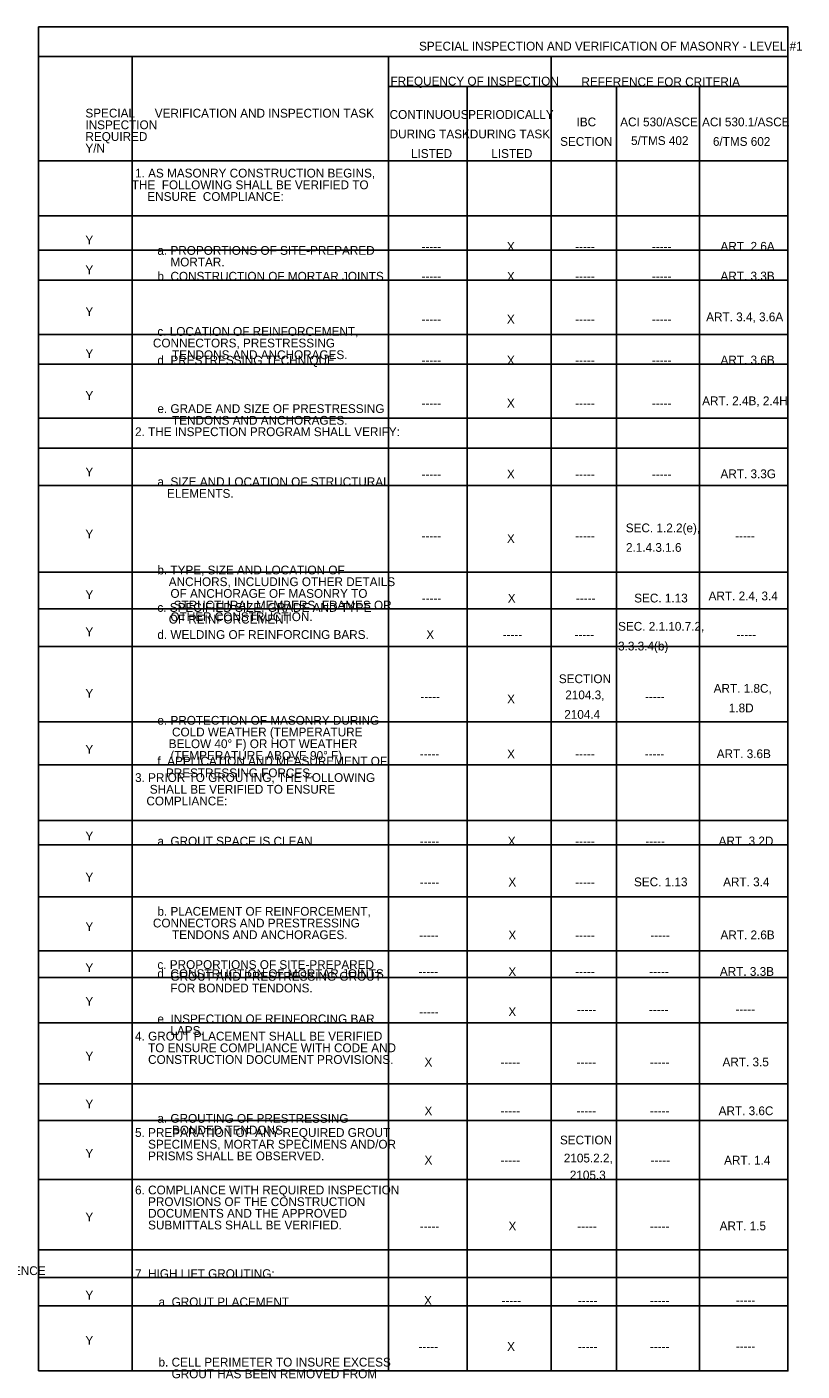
# Model space of a CAD drawing. Extents: x 2632118 to 2632142.4, y 1706724.1 to 1706788.4.
# Drawn here: x 2632127.48 to 2632134.83, y 1706755.03 to 1706767.77 of the extents above; entities that cross this region are included whole.
import ezdxf

# ---------------------------------------------------------------- set-up
doc = ezdxf.new("R2010")
doc.units = 0
doc.layers.add('Default', color=7, linetype='Continuous')

msp = doc.modelspace()

# ---------------------------------------------------------------- linework, layer by layer
at = {"layer": 'Default'}
for p, q in [((2632128.477, 1706767.493), (2632128.477, 1706755.032)), ((2632130.909, 1706767.493), (2632130.909, 1706755.032)), ((2632132.454, 1706767.493), (2632132.454, 1706755.032)), ((2632134.699, 1706767.211), (2632130.909, 1706767.211)), ((2632131.655, 1706767.211), (2632131.655, 1706755.032)), ((2632133.074, 1706767.211), (2632133.074, 1706755.032)), ((2632133.861, 1706767.211), (2632133.861, 1706755.032)), ((2632134.699, 1706766.505), (2632127.588, 1706766.505)), ((2632134.699, 1706765.984), (2632127.588, 1706765.984)), ((2632134.699, 1706765.657), (2632127.588, 1706765.657)), ((2632134.699, 1706765.374), (2632127.588, 1706765.374)), ((2632134.699, 1706764.86), (2632127.588, 1706764.86)), ((2632134.699, 1706764.578), (2632127.588, 1706764.578)), ((2632134.699, 1706764.064), (2632127.588, 1706764.064)), ((2632134.699, 1706763.782), (2632127.588, 1706763.782)), ((2632134.699, 1706763.427), (2632127.588, 1706763.427)), ((2632134.699, 1706762.604), (2632127.588, 1706762.604)), ((2632134.699, 1706762.256), (2632127.588, 1706762.256)), ((2632134.699, 1706761.899), (2632127.588, 1706761.899)), ((2632134.699, 1706761.187), (2632127.588, 1706761.187)), ((2632134.699, 1706760.777), (2632127.588, 1706760.777)), ((2632134.699, 1706760.25), (2632127.588, 1706760.25)), ((2632134.699, 1706760.019), (2632127.588, 1706760.019)), ((2632134.699, 1706759.528), (2632127.588, 1706759.528)), ((2632134.699, 1706759.015), (2632127.588, 1706759.015)), ((2632134.699, 1706758.762), (2632127.588, 1706758.762)), ((2632134.699, 1706758.334), (2632127.588, 1706758.334)), ((2632134.699, 1706757.753), (2632127.588, 1706757.753)), ((2632134.699, 1706757.405), (2632127.588, 1706757.405)), ((2632134.699, 1706756.846), (2632127.588, 1706756.846)), ((2632134.699, 1706756.179), (2632127.588, 1706756.179)), ((2632134.699, 1706755.919), (2632127.588, 1706755.919)), ((2632134.699, 1706755.651), (2632127.588, 1706755.651))]:
    msp.add_line(p, q, dxfattribs=at)
msp.add_lwpolyline([(2632127.588, 1706755.032), (2632134.699, 1706755.032), (2632134.699, 1706767.775), (2632127.588, 1706767.775)], close=True, dxfattribs=at)
msp.add_lwpolyline([(2632134.699, 1706767.493), (2632127.588, 1706767.493)], dxfattribs=at)

# ---------------------------------------------------------------- texts
for s, height, p in [('SPECIAL INSPECTION AND VERIFICATION OF MASONRY - LEVEL #1 ', 0.08333, (2632131.199, 1706767.551)), ('FREQUENCY OF INSPECTION ', 0.08333, (2632130.928, 1706767.219)), ('REFERENCE FOR CRITERIA', 0.08333, (2632132.74, 1706767.213)), ('SPECIAL ', 0.0833, (2632128.033, 1706766.916)), ('VERIFICATION AND INSPECTION TASK ', 0.08333, (2632128.691, 1706766.915)), ('INSPECTION ', 0.08333, (2632128.033, 1706766.805)), ('CONTINUOUS', 0.0833, (2632130.92, 1706766.903)), ('PERIODICALLY', 0.08333, (2632131.665, 1706766.903)), ('IBC', 0.0833, (2632132.694, 1706766.832)), ('ACI 530/ASCE', 0.08333, (2632133.108, 1706766.832)), ('ACI 530.1/ASCE', 0.08333, (2632133.885, 1706766.832)), ('REQUIRED', 0.0833, (2632128.033, 1706766.694)), ('DURING TASK', 0.08333, (2632130.92, 1706766.718)), ('DURING TASK', 0.08333, (2632131.681, 1706766.718)), ('5/TMS 402', 0.0833, (2632133.211, 1706766.655)), ('Y/N', 0.0833, (2632128.033, 1706766.583)), ('LISTED', 0.0833, (2632131.123, 1706766.533)), ('LISTED', 0.0833, (2632131.885, 1706766.533)), ('SECTION', 0.0833, (2632132.538, 1706766.647)), ('6/TMS 602', 0.0833, (2632133.988, 1706766.647)), ('1. AS MASONRY CONSTRUCTION BEGINS, ', 0.08333, (2632128.504, 1706766.347)), ('   THE  FOLLOWING SHALL BE VERIFIED TO ', 0.08333, (2632128.38, 1706766.236)), ('   ENSURE  COMPLIANCE:', 0.08333, (2632128.528, 1706766.125)), ('Y', 0.0833, (2632128.033, 1706765.712)), ('X', 0.0833, (2632132.033, 1706765.651)), ('ART. 2.6A', 0.0833, (2632134.06, 1706765.653)), ('a. PROPORTIONS OF SITE-PREPARED ', 0.08333, (2632128.716, 1706765.614)), ('-----', 0.0833, (2632131.223, 1706765.651)), ('-----', 0.0833, (2632132.681, 1706765.651)), ('-----', 0.0833, (2632133.409, 1706765.651)), ('Y', 0.0833, (2632128.033, 1706765.43)), ('    MORTAR.', 0.08333, (2632128.716, 1706765.504)), ('b. CONSTRUCTION OF MORTAR JOINTS.', 0.08333, (2632128.716, 1706765.369)), ('-----', 0.0833, (2632131.223, 1706765.369)), ('X', 0.0833, (2632132.033, 1706765.369)), ('-----', 0.0833, (2632132.681, 1706765.369)), ('-----', 0.0833, (2632133.409, 1706765.369)), ('ART. 3.3B', 0.0833, (2632134.06, 1706765.371)), ('Y', 0.0833, (2632128.033, 1706765.034)), ('-----', 0.0833, (2632131.223, 1706764.962)), ('X', 0.0833, (2632132.033, 1706764.962)), ('-----', 0.0833, (2632132.681, 1706764.962)), ('-----', 0.0833, (2632133.409, 1706764.962)), ('ART. 3.4, 3.6A', 0.08333, (2632133.924, 1706764.984)), ('c. LOCATION OF REINFORCEMENT, ', 0.08333, (2632128.716, 1706764.846)), ('Y', 0.0833, (2632128.033, 1706764.636)), ('    CONNECTORS, PRESTRESSING ', 0.08333, (2632128.55, 1706764.736)), ('    TENDONS AND ANCHORAGES.', 0.08333, (2632128.731, 1706764.625)), ('d. PRESTRESSING TECHNIQUE', 0.08333, (2632128.716, 1706764.573)), ('-----', 0.0833, (2632131.223, 1706764.573)), ('X', 0.0833, (2632132.033, 1706764.573)), ('-----', 0.0833, (2632132.681, 1706764.573)), ('-----', 0.0833, (2632133.409, 1706764.573)), ('ART. 3.6B', 0.0833, (2632134.06, 1706764.575)), ('Y', 0.0833, (2632128.033, 1706764.238)), ('e. GRADE AND SIZE OF PRESTRESSING ', 0.08333, (2632128.716, 1706764.114)), ('-----', 0.0833, (2632131.223, 1706764.166)), ('X', 0.0833, (2632132.033, 1706764.166)), ('-----', 0.0833, (2632132.681, 1706764.166)), ('-----', 0.0833, (2632133.409, 1706764.166)), ('ART. 2.4B, 2.4H', 0.08333, (2632133.886, 1706764.188)), ('    TENDONS AND ANCHORAGES.', 0.08333, (2632128.731, 1706764.003)), ('2. THE INSPECTION PROGRAM SHALL VERIFY:', 0.08333, (2632128.504, 1706763.895)), ('Y', 0.0833, (2632128.033, 1706763.514)), ('X', 0.0833, (2632132.033, 1706763.494)), ('ART. 3.3G', 0.0833, (2632134.06, 1706763.496)), ('a. SIZE AND LOCATION OF STRUCTURAL ', 0.08333, (2632128.716, 1706763.421)), ('-----', 0.0833, (2632131.223, 1706763.494)), ('-----', 0.0833, (2632132.681, 1706763.494)), ('-----', 0.0833, (2632133.409, 1706763.494)), ('    ELEMENTS.', 0.08333, (2632128.684, 1706763.31)), ('SEC. 1.2.2(e),', 0.08333, (2632133.161, 1706762.983)), ('Y', 0.0833, (2632128.033, 1706762.925)), ('-----', 0.0833, (2632131.223, 1706762.907)), ('X', 0.0833, (2632132.033, 1706762.882)), ('-----', 0.0833, (2632132.681, 1706762.907)), ('-----', 0.0833, (2632134.199, 1706762.907)), ('2.1.4.3.1.6', 0.08333, (2632133.163, 1706762.798)), ('b. TYPE, SIZE AND LOCATION OF ', 0.08333, (2632128.716, 1706762.584)), ('    ANCHORS, INCLUDING OTHER DETAILS ', 0.08333, (2632128.7, 1706762.473)), ('Y', 0.0833, (2632128.033, 1706762.35)), ('    OF ANCHORAGE OF MASONRY TO', 0.08333, (2632128.716, 1706762.362)), ('ART. 2.4, 3.4', 0.08333, (2632133.947, 1706762.338)), ('c. SPECIFIED SIZE, GRADE AND TYPE ', 0.08333, (2632128.716, 1706762.229)), ('    STRUCTURAL MEMBERS, FRAMES OR ', 0.08333, (2632128.747, 1706762.251)), ('-----', 0.0833, (2632131.225, 1706762.316)), ('X', 0.0833, (2632132.041, 1706762.316)), ('-----', 0.0833, (2632132.688, 1706762.316)), ('SEC. 1.13', 0.0833, (2632133.241, 1706762.318)), ('    OF REINFORCEMENT', 0.08333, (2632128.7, 1706762.118)), ('    OTHER CONSTRUCTION.', 0.08333, (2632128.716, 1706762.141)), ('Y', 0.0833, (2632128.033, 1706761.998)), ('d. WELDING OF REINFORCING BARS.', 0.08333, (2632128.716, 1706761.972)), ('X', 0.0833, (2632131.268, 1706761.972)), ('SEC. 2.1.10.7.2,', 0.08333, (2632133.088, 1706762.05)), ('-----', 0.0833, (2632131.993, 1706761.972)), ('-----', 0.0833, (2632132.675, 1706761.972)), ('3.3.3.4(b)', 0.0833, (2632133.088, 1706761.863)), ('-----', 0.0833, (2632134.212, 1706761.972)), ('SECTION', 0.0833, (2632132.526, 1706761.553)), ('ART. 1.8C,', 0.0833, (2632133.995, 1706761.462)), ('Y', 0.0833, (2632128.033, 1706761.415)), ('-----', 0.0833, (2632131.212, 1706761.385)), ('X', 0.0833, (2632132.035, 1706761.361)), ('2104.3,', 0.0833, (2632132.587, 1706761.4)), ('-----', 0.0833, (2632133.344, 1706761.385)), ('2104.4', 0.0833, (2632132.577, 1706761.215)), ('1.8D', 0.0833, (2632134.139, 1706761.276)), ('e. PROTECTION OF MASONRY DURING ', 0.08333, (2632128.716, 1706761.159)), ('    COLD WEATHER (TEMPERATURE ', 0.08333, (2632128.731, 1706761.048)), ('    BELOW 40%%d F) OR HOT WEATHER', 0.08333, (2632128.7, 1706760.937)), ('Y', 0.0833, (2632128.033, 1706760.884)), ('    (TEMPERATURE ABOVE 90%%d F)', 0.08333, (2632128.716, 1706760.826)), ('X', 0.0833, (2632132.035, 1706760.84)), ('ART. 3.6B', 0.0833, (2632134.024, 1706760.842)), ('f. APPLICATION AND MEASUREMENT OF ', 0.08333, (2632128.716, 1706760.772)), ('-----', 0.0833, (2632131.206, 1706760.84)), ('-----', 0.0833, (2632132.681, 1706760.84)), ('-----', 0.0833, (2632133.341, 1706760.84)), ('3. PRIOR TO GROUTING, THE FOLLOWING ', 0.08333, (2632128.504, 1706760.616)), ('   PRESTRESSING FORCES.', 0.08333, (2632128.704, 1706760.661)), ('    SHALL BE VERIFIED TO ENSURE ', 0.08333, (2632128.52, 1706760.505)), ('    COMPLIANCE:', 0.08333, (2632128.488, 1706760.394)), ('Y', 0.0833, (2632128.033, 1706760.062)), ('a. GROUT SPACE IS CLEAN.', 0.08333, (2632128.716, 1706760.013)), ('-----', 0.0833, (2632131.206, 1706760.013)), ('X', 0.0833, (2632132.041, 1706760.013)), ('-----', 0.0833, (2632132.681, 1706760.013)), ('-----', 0.0833, (2632133.347, 1706760.013)), ('ART. 3.2D', 0.0833, (2632134.042, 1706760.015)), ('Y', 0.0833, (2632128.033, 1706759.672)), ('-----', 0.0833, (2632131.206, 1706759.625)), ('X', 0.0833, (2632132.047, 1706759.625)), ('-----', 0.0833, (2632132.681, 1706759.625)), ('SEC. 1.13', 0.0833, (2632133.239, 1706759.627)), ('ART. 3.4', 0.0833, (2632134.085, 1706759.627)), ('b. PLACEMENT OF REINFORCEMENT, ', 0.08333, (2632128.716, 1706759.348)), ('Y', 0.0833, (2632128.033, 1706759.203)), ('    CONNECTORS AND PRESTRESSING ', 0.08333, (2632128.55, 1706759.237)), ('    TENDONS AND ANCHORAGES. ', 0.08333, (2632128.731, 1706759.126)), ('-----', 0.0833, (2632131.2, 1706759.123)), ('X', 0.0833, (2632132.047, 1706759.123)), ('-----', 0.0833, (2632132.681, 1706759.123)), ('-----', 0.0833, (2632133.394, 1706759.123)), ('ART. 2.6B', 0.0833, (2632134.06, 1706759.125)), ('Y', 0.0833, (2632128.033, 1706758.813)), ('c. PROPORTIONS OF SITE-PREPARED ', 0.08333, (2632128.716, 1706758.843)), ('d. CONSTRUCTION OF MORTAR JOINTS.', 0.08333, (2632128.716, 1706758.757)), ('X', 0.0833, (2632132.047, 1706758.776)), ('ART. 3.3B', 0.0833, (2632134.054, 1706758.778)), ('    GROUT AND PRESTRESSING GROUT ', 0.08333, (2632128.716, 1706758.732)), ('-----', 0.0833, (2632131.194, 1706758.776)), ('-----', 0.0833, (2632132.681, 1706758.776)), ('-----', 0.0833, (2632133.384, 1706758.776)), ('    FOR BONDED TENDONS. ', 0.08333, (2632128.716, 1706758.621)), ('Y', 0.0833, (2632128.033, 1706758.494)), ('X', 0.0833, (2632132.047, 1706758.396)), ('-----', 0.0833, (2632134.202, 1706758.42)), ('e. INSPECTION OF REINFORCING BAR ', 0.08333, (2632128.716, 1706758.328)), ('-----', 0.0833, (2632131.2, 1706758.396)), ('-----', 0.0833, (2632132.696, 1706758.417)), ('-----', 0.0833, (2632133.381, 1706758.417)), ('4. GROUT PLACEMENT SHALL BE VERIFIED ', 0.08333, (2632128.504, 1706758.165)), ('    LAPS.', 0.0833, (2632128.716, 1706758.218)), ('    TO ENSURE COMPLIANCE WITH CODE AND ', 0.08333, (2632128.504, 1706758.054)), ('Y', 0.0833, (2632128.033, 1706757.975)), ('    CONSTRUCTION DOCUMENT PROVISIONS.', 0.08333, (2632128.504, 1706757.943)), ('X', 0.0833, (2632131.251, 1706757.918)), ('-----', 0.0833, (2632131.972, 1706757.918)), ('-----', 0.0833, (2632132.694, 1706757.918)), ('-----', 0.0833, (2632133.39, 1706757.918)), ('ART. 3.5', 0.0833, (2632134.079, 1706757.92)), ('Y', 0.0833, (2632128.033, 1706757.521)), ('a. GROUTING OF PRESTRESSING ', 0.08333, (2632128.716, 1706757.385)), ('X', 0.0833, (2632131.251, 1706757.455)), ('-----', 0.0833, (2632131.972, 1706757.455)), ('-----', 0.0833, (2632132.694, 1706757.455)), ('-----', 0.0833, (2632133.39, 1706757.455)), ('ART. 3.6C', 0.0833, (2632134.042, 1706757.457)), ('5. PREPARATION OF ANY REQUIRED GROUT ', 0.08333, (2632128.504, 1706757.251)), ('    BONDED TENDONS', 0.08333, (2632128.731, 1706757.274)), ('    SPECIMENS, MORTAR SPECIMENS AND/OR ', 0.08333, (2632128.504, 1706757.14)), ('SECTION', 0.0833, (2632132.536, 1706757.18)), ('Y', 0.0833, (2632128.033, 1706757.053)), ('    PRISMS SHALL BE OBSERVED.', 0.08333, (2632128.504, 1706757.029)), ('X', 0.0833, (2632131.251, 1706756.989)), ('2105.2.2,', 0.0833, (2632132.573, 1706757.009)), ('ART. 1.4', 0.0833, (2632134.094, 1706756.989)), ('-----', 0.0833, (2632131.972, 1706756.989)), ('2105.3', 0.0833, (2632132.63, 1706756.848)), ('-----', 0.0833, (2632133.396, 1706756.989)), ('6. COMPLIANCE WITH REQUIRED INSPECTION ', 0.08333, (2632128.504, 1706756.706)), ('    PROVISIONS OF THE CONSTRUCTION ', 0.08333, (2632128.504, 1706756.595)), ('    DOCUMENTS AND THE APPROVED ', 0.08333, (2632128.504, 1706756.485)), ('Y', 0.0833, (2632128.033, 1706756.45)), ('    SUBMITTALS SHALL BE VERIFIED.', 0.08333, (2632128.504, 1706756.374)), ('X', 0.0833, (2632132.048, 1706756.364)), ('ART. 1.5', 0.0833, (2632134.052, 1706756.366)), ('-----', 0.0833, (2632131.206, 1706756.364)), ('-----', 0.0833, (2632132.7, 1706756.364)), ('-----', 0.0833, (2632133.39, 1706756.364)), ('REFERENCE', 0.0833, (2632126.968, 1706755.941)), ('7. HIGH LIFT GROUTING:', 0.08333, (2632128.504, 1706755.913)), ('Y', 0.0833, (2632128.033, 1706755.709)), ('a. GROUT PLACEMENT.', 0.08333, (2632128.727, 1706755.645)), ('X', 0.0833, (2632131.247, 1706755.659)), ('-----', 0.0833, (2632131.982, 1706755.659)), ('-----', 0.0833, (2632132.706, 1706755.659)), ('-----', 0.0833, (2632133.39, 1706755.659)), ('-----', 0.0833, (2632134.205, 1706755.662)), ('Y', 0.0833, (2632128.033, 1706755.28)), ('X', 0.0833, (2632132.035, 1706755.222)), ('b. CELL PERIMETER TO INSURE EXCESS ', 0.08333, (2632128.727, 1706755.074)), ('-----', 0.0833, (2632131.194, 1706755.222)), ('-----', 0.0833, (2632132.706, 1706755.222)), ('-----', 0.0833, (2632133.39, 1706755.222)), ('-----', 0.0833, (2632134.205, 1706755.225)), ('    GROUT HAS BEEN REMOVED FROM ', 0.08333, (2632128.727, 1706754.963))]:
    msp.add_text(s, height=height, dxfattribs=at).set_placement(p)

doc.saveas('drawing.dxf')
